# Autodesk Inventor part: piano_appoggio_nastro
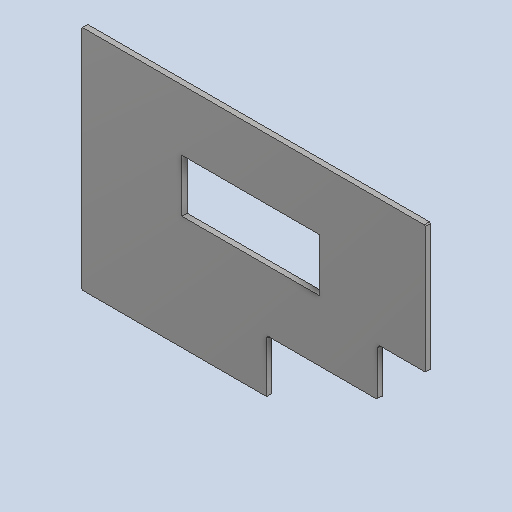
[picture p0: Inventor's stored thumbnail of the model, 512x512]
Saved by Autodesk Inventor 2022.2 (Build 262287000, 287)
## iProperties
Created: 2024-10
Part Number: piano_appoggio_nastro
Material: Alluminio 6061
Document SubType Name: Modeling
Designer: 18907419
Density: 2.7 g/cm^3
Appearance: Default
Author: 18907419
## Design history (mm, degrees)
feature "Solido1"
node "Solido2"
